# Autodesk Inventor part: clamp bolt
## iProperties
Shininess: 64.0
Length Units: 11272
Angle Units: 11279
Time Units: 11290
Mass Units: 11286
Length Display Precision: 3
Compacted: True
Part Number: clamp bolt
Document SubType Name: Modeling
Created: 2002-11
Designer: E. MOSS
Density: 0.0
Volumn: 0.0
Area: 0.0
PropertySet Name: Model Information
Control State: 0
Master: False
Checked Out: False
Author: E. MOSS
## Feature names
1. Extrusion1
2. Hole1
